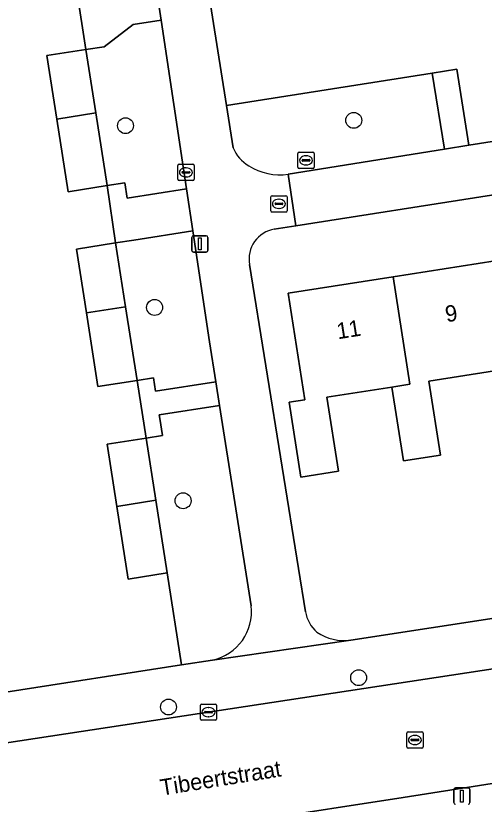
# Model space of a CAD drawing. Extents: x 160077 to 160948, y 386481 to 387498.
# Drawn here: x 160386.76 to 160415.56, y 387278.08 to 387326.58 of the extents above; entities that cross this region are included whole.
import ezdxf

# ---------------------------------------------------------------- set-up
doc = ezdxf.new("R2010")
doc.units = 0
for name, color, linetype in [('IMGEO_Boom', 7, 'Continuous'), ('IMGEO_Brandkraan', 7, 'Continuous'), ('IMGEO_Erf', 7, 'Continuous'), ('IMGEO_Groenvoorziening', 7, 'Continuous'), ('IMGEO_Kolk', 7, 'Continuous'), ('IMGEO_Lichtmast', 7, 'Continuous'), ('IMGEO_Openbare_ruimte_label', 7, 'Continuous'), ('IMGEO_Pand', 7, 'Continuous'), ('IMGEO_Pand_nummerreeks', 7, 'Continuous'), ('IMGEO_Rijbaan_lokaal_open', 7, 'Continuous'), ('IMGEO_Rioolput', 7, 'Continuous'), ('IMGEO_Voetpad_open', 7, 'Continuous')]:
    doc.layers.add(name, color=color, linetype=linetype)

msp = doc.modelspace()

# ---------------------------------------------------------------- linework, layer by layer
at = {"layer": 'IMGEO_Boom'}
for centre in [(160393.501, 387319.82), (160407.54, 387320.148), (160395.293, 387308.64), (160397.045, 387296.749), (160407.841, 387285.863), (160396.15, 387284.06)]:
    msp.add_circle(centre, 0.489, dxfattribs=at)
at = {"layer": 'IMGEO_Brandkraan'}
for p, q in [((160402.513, 387315.511), (160403.365, 387315.511)), ((160402.438, 387314.585), (160402.438, 387315.437)), ((160402.697, 387315.005), (160402.697, 387315.017)), ((160403.135, 387314.968), (160402.737, 387314.968)), ((160402.74, 387315.054), (160403.138, 387315.054)), ((160402.926, 387315.291), (160402.951, 387315.291)), ((160403.181, 387315.017), (160403.181, 387315.005)), ((160403.439, 387315.437), (160403.439, 387314.585)), ((160403.365, 387314.511), (160402.513, 387314.511)), ((160402.949, 387314.731), (160402.924, 387314.731))]:
    msp.add_line(p, q, dxfattribs=at)
for points in [[(160402.513, 387315.511), (160403.365, 387315.511)], [(160402.438, 387314.585), (160402.438, 387315.437)], [(160403.439, 387315.437), (160403.439, 387314.585)], [(160403.365, 387314.511), (160402.513, 387314.511)]]:
    msp.add_lwpolyline(points, dxfattribs=at)
for centre, radius, start, end in [((160402.515, 387315.435), 0.0765, 91.552, 178.448), ((160402.515, 387315.435), 0.0765, 91.552, 178.448), ((160403.363, 387315.435), 0.0765, 1.552, 88.448), ((160403.363, 387315.435), 0.0765, 1.552, 88.448), ((160402.737, 387315.014), 0.0403, 85.8775, 175.7526), ((160402.734, 387315.004), 0.0366, 178.938, 274.7102), ((160403.138, 387315.011), 0.043, 264.8664, 352.4533), ((160403.142, 387315.016), 0.0386, 1.7309, 96.639), ((160402.515, 387314.587), 0.0765, 181.552, 268.448), ((160402.515, 387314.587), 0.0765, 181.552, 268.448), ((160403.363, 387314.587), 0.0765, 271.552, 358.448), ((160403.363, 387314.587), 0.0765, 271.552, 358.448)]:
    msp.add_arc(centre, radius, start, end, dxfattribs=at)
for centre, major_axis, ratio, start_param, end_param in [((160402.925, 387315.011), (-0.387, 0.002), 0.722429, 4.712389, 7.853982), ((160402.95, 387315.011), (-0.39, 0.002), 0.717154, 1.570796, 4.712389)]:
    msp.add_ellipse(centre, major_axis=major_axis, ratio=ratio, start_param=start_param, end_param=end_param, dxfattribs=at)
at = {"layer": 'IMGEO_Erf'}
for points in [[(160396.716, 387339.967), (160399.712, 387321.067), (160412.37, 387323.056), (160413.879, 387323.293), (160414.621, 387318.615), (160420.12, 387319.489), (160421.491, 387319.707), (160425.074, 387320.276), (160424.333, 387324.945), (160425.392, 387325.112), (160425.675, 387325.157), (160426.301, 387321.22), (160440.954, 387323.546)], [(160375.322, 387283.298), (160396.951, 387286.648), (160396.068, 387292.305), (160393.663, 387291.93), (160392.965, 387296.404), (160392.369, 387300.222), (160394.774, 387300.597), (160394.213, 387304.145), (160391.808, 387303.77), (160391.099, 387308.315), (160390.488, 387312.232), (160392.893, 387312.607), (160392.376, 387316.133), (160389.972, 387315.758), (160389.274, 387320.231), (160388.665, 387324.131), (160391.07, 387324.506), (160390.513, 387328.113), (160388.108, 387327.738), (160387.421, 387332.143)], [(160440.073, 387319.313), (160403.977, 387313.658), (160402.655, 387313.451)], [(160401.131, 387311.289), (160404.14, 387292.577), (160404.567, 387289.922)], [(160416.185, 387304.734), (160412.166, 387304.104), (160412.878, 387299.557), (160410.591, 387299.199), (160409.879, 387303.745), (160405.887, 387303.12), (160406.599, 387298.573), (160404.28, 387298.209), (160403.56, 387302.803), (160404.534, 387302.956), (160403.505, 387309.521), (160409.959, 387310.532), (160416.235, 387311.515)], [(160407.359, 387288.172), (160412.298, 387288.928), (160417.775, 387289.765), (160417.165, 387293.754), (160416.344, 387293.629), (160416.158, 387294.849), (160416.464, 387294.895), (160419.053, 387295.291), (160419.238, 387294.071), (160418.704, 387293.99), (160419.314, 387290), (160443.963, 387293.77)]]:
    msp.add_lwpolyline(points, dxfattribs=at)
for centre, radius, start, end in [((160402.963, 387311.616), 1.861, 99.5237, 190.1161), ((160406.729, 387290.297), 2.194, 189.8286, 228.4264), ((160406.969, 387291.235), 3.088, 236.6785, 277.2481)]:
    msp.add_arc(centre, radius, start, end, dxfattribs=at)
at = {"layer": 'IMGEO_Groenvoorziening'}
for points in [[(160395.697, 387326.317), (160393.978, 387326.046), (160392.194, 387324.68), (160391.07, 387324.506), (160391.679, 387320.602), (160392.376, 387316.133), (160393.466, 387316.301), (160393.613, 387315.369), (160397.255, 387315.946)], [(160397.646, 387313.348), (160394.019, 387312.781), (160392.893, 387312.607), (160393.505, 387308.686), (160394.213, 387304.145), (160395.223, 387304.301), (160395.352, 387303.483), (160399.059, 387304.069), (160398.671, 387306.527)]]:
    msp.add_lwpolyline(points, close=True, dxfattribs=at)
for points in [[(160412.37, 387323.056), (160399.712, 387321.067), (160400.128, 387318.456)], [(160403.511, 387316.844), (160413.113, 387318.38), (160412.37, 387323.056)], [(160399.289, 387302.614), (160395.581, 387302.029), (160395.614, 387301.817), (160395.781, 387300.753), (160394.774, 387300.597), (160395.37, 387296.775), (160396.068, 387292.305), (160396.951, 387286.648), (160398.856, 387286.944)], [(160401.235, 387290.289), (160399.289, 387302.614)]]:
    msp.add_lwpolyline(points, dxfattribs=at)
for centre, radius, start, end in [((160402.16, 387319.269), 2.189, 201.8011, 240.7553), ((160402.959, 387320.195), 3.396, 236.6257, 279.3465), ((160398.192, 387289.935), 3.064, 282.5179, 6.6404)]:
    msp.add_arc(centre, radius, start, end, dxfattribs=at)
at = {"layer": 'IMGEO_Kolk'}
for p, q in [((160396.794, 387317.448), (160397.646, 387317.448)), ((160396.719, 387316.522), (160396.719, 387317.374)), ((160396.978, 387316.942), (160396.978, 387316.954)), ((160397.416, 387316.905), (160397.018, 387316.905)), ((160397.021, 387316.991), (160397.419, 387316.991)), ((160397.207, 387317.228), (160397.232, 387317.228)), ((160397.462, 387316.954), (160397.462, 387316.942)), ((160397.72, 387317.374), (160397.72, 387316.522)), ((160397.646, 387316.448), (160396.794, 387316.448)), ((160397.23, 387316.668), (160397.205, 387316.668)), ((160398.107, 387283.318), (160398.107, 387284.17)), ((160398.182, 387284.244), (160399.034, 387284.244)), ((160398.595, 387284.024), (160398.62, 387284.024)), ((160399.108, 387284.17), (160399.108, 387283.318)), ((160398.366, 387283.738), (160398.366, 387283.75)), ((160398.804, 387283.701), (160398.406, 387283.701)), ((160398.409, 387283.787), (160398.807, 387283.787)), ((160398.618, 387283.464), (160398.593, 387283.464)), ((160398.85, 387283.75), (160398.85, 387283.738)), ((160399.034, 387283.244), (160398.182, 387283.244))]:
    msp.add_line(p, q, dxfattribs=at)
for points in [[(160396.794, 387317.448), (160397.646, 387317.448)], [(160396.719, 387316.522), (160396.719, 387317.374)], [(160397.72, 387317.374), (160397.72, 387316.522)], [(160397.646, 387316.448), (160396.794, 387316.448)], [(160398.107, 387283.318), (160398.107, 387284.17)], [(160398.182, 387284.244), (160399.034, 387284.244)], [(160399.108, 387284.17), (160399.108, 387283.318)], [(160399.034, 387283.244), (160398.182, 387283.244)]]:
    msp.add_lwpolyline(points, dxfattribs=at)
for centre, radius, start, end in [((160396.796, 387317.372), 0.0765, 91.552, 178.448), ((160396.796, 387317.372), 0.0765, 91.552, 178.448), ((160397.644, 387317.372), 0.0765, 1.552, 88.448), ((160397.644, 387317.372), 0.0765, 1.552, 88.448), ((160397.018, 387316.951), 0.0403, 85.8775, 175.7526), ((160397.015, 387316.941), 0.0366, 178.938, 274.7102), ((160397.419, 387316.948), 0.043, 264.8664, 352.4533), ((160397.423, 387316.953), 0.0386, 1.7309, 96.639), ((160396.796, 387316.524), 0.0765, 181.552, 268.448), ((160396.796, 387316.524), 0.0765, 181.552, 268.448), ((160397.644, 387316.524), 0.0765, 271.552, 358.448), ((160397.644, 387316.524), 0.0765, 271.552, 358.448), ((160398.184, 387284.168), 0.0765, 91.552, 178.448), ((160398.184, 387284.168), 0.0765, 91.552, 178.448), ((160399.032, 387284.168), 0.0765, 1.552, 88.448), ((160399.032, 387284.168), 0.0765, 1.552, 88.448), ((160398.406, 387283.747), 0.0403, 85.8775, 175.7526), ((160398.403, 387283.737), 0.0366, 178.938, 274.7102), ((160398.807, 387283.744), 0.043, 264.8664, 352.4533), ((160398.811, 387283.749), 0.0386, 1.7309, 96.639), ((160398.184, 387283.32), 0.0765, 181.552, 268.448), ((160398.184, 387283.32), 0.0765, 181.552, 268.448), ((160399.032, 387283.32), 0.0765, 271.552, 358.448), ((160399.032, 387283.32), 0.0765, 271.552, 358.448)]:
    msp.add_arc(centre, radius, start, end, dxfattribs=at)
for centre, major_axis, ratio, start_param, end_param in [((160397.206, 387316.948), (-0.387, 0.002), 0.722429, 4.712389, 7.853982), ((160397.231, 387316.948), (-0.39, 0.002), 0.717154, 1.570796, 4.712389), ((160398.594, 387283.744), (-0.387, 0.002), 0.722429, 4.712389, 7.853982), ((160398.619, 387283.744), (-0.39, 0.002), 0.717154, 1.570796, 4.712389)]:
    msp.add_ellipse(centre, major_axis=major_axis, ratio=ratio, start_param=start_param, end_param=end_param, dxfattribs=at)
at = {"layer": 'IMGEO_Lichtmast'}
for p, q in [((160397.679, 387313.05), (160398.469, 387313.05)), ((160398.469, 387313.05), (160397.679, 387313.05)), ((160397.579, 387312.15), (160397.579, 387312.95)), ((160397.579, 387312.95), (160397.579, 387312.15)), ((160398.569, 387312.95), (160398.569, 387312.15)), ((160398.569, 387312.15), (160398.569, 387312.95)), ((160398.469, 387312.05), (160397.679, 387312.05)), ((160397.679, 387312.05), (160398.469, 387312.05)), ((160413.793, 387279.079), (160414.583, 387279.079)), ((160414.583, 387279.079), (160413.793, 387279.079)), ((160413.693, 387278.179), (160413.693, 387278.979)), ((160413.693, 387278.979), (160413.693, 387278.179)), ((160414.683, 387278.979), (160414.683, 387278.179)), ((160414.683, 387278.179), (160414.683, 387278.979))]:
    msp.add_line(p, q, dxfattribs=at)
for points in [[(160397.999, 387312.925), (160398.149, 387312.925), (160398.149, 387312.175), (160397.999, 387312.175), (160397.999, 387312.925)], [(160414.113, 387278.954), (160414.263, 387278.954), (160414.263, 387278.204), (160414.113, 387278.204), (160414.113, 387278.954)]]:
    msp.add_lwpolyline(points, dxfattribs=at)
for centre, start, end in [((160397.679, 387312.95), 90, 180), ((160397.679, 387312.95), 90, 180), ((160398.469, 387312.95), 0, 90), ((160398.469, 387312.95), 360, 90), ((160397.679, 387312.15), 180, 270), ((160397.679, 387312.15), 180, 270), ((160398.469, 387312.15), 270, 0), ((160398.469, 387312.15), 270, 0), ((160413.793, 387278.979), 90, 180), ((160413.793, 387278.979), 90, 180), ((160414.583, 387278.979), 0, 90), ((160414.583, 387278.979), 360, 90), ((160413.793, 387278.179), 180, 270), ((160413.793, 387278.179), 180, 270), ((160414.583, 387278.179), 270, 0), ((160414.583, 387278.179), 270, 0)]:
    msp.add_arc(centre, 0.1, start, end, dxfattribs=at)
at = {"layer": 'IMGEO_Pand'}
for points in [[(160391.07, 387324.506), (160388.665, 387324.131), (160389.274, 387320.231), (160391.679, 387320.602)], [(160391.679, 387320.602), (160389.274, 387320.231), (160389.972, 387315.758), (160392.376, 387316.133)], [(160392.893, 387312.607), (160390.488, 387312.232), (160391.099, 387308.315), (160393.505, 387308.686)], [(160417.27, 387304.905), (160416.235, 387311.515), (160409.959, 387310.532), (160410.995, 387303.919), (160409.879, 387303.745), (160410.591, 387299.199), (160412.878, 387299.557), (160412.166, 387304.104), (160416.185, 387304.734)], [(160410.995, 387303.919), (160409.959, 387310.532), (160403.505, 387309.521), (160404.534, 387302.956), (160403.56, 387302.803), (160404.28, 387298.209), (160406.599, 387298.573), (160405.887, 387303.12), (160409.879, 387303.745)], [(160393.505, 387308.686), (160391.099, 387308.315), (160391.808, 387303.77), (160394.213, 387304.145)], [(160394.774, 387300.597), (160392.369, 387300.222), (160392.965, 387296.404), (160395.37, 387296.775)], [(160395.37, 387296.775), (160392.965, 387296.404), (160393.663, 387291.93), (160396.068, 387292.305)]]:
    msp.add_lwpolyline(points, close=True, dxfattribs=at)
at = {"layer": 'IMGEO_Rijbaan_lokaal_open'}
for points in [[(160444.411, 387290.851), (160417.322, 387286.585), (160375.933, 387280.299)], [(160397.338, 387276.443), (160401.538, 387277.092), (160410.581, 387278.491), (160447.213, 387284.258)]]:
    msp.add_lwpolyline(points, dxfattribs=at)
at = {"layer": 'IMGEO_Rioolput'}
for p, q in [((160404.103, 387317.264), (160404.103, 387318.116)), ((160404.178, 387318.19), (160405.03, 387318.19)), ((160404.591, 387317.97), (160404.616, 387317.97)), ((160405.104, 387318.116), (160405.104, 387317.264)), ((160404.362, 387317.684), (160404.362, 387317.696)), ((160404.8, 387317.647), (160404.402, 387317.647)), ((160404.405, 387317.733), (160404.803, 387317.733)), ((160404.614, 387317.41), (160404.589, 387317.41)), ((160404.846, 387317.696), (160404.846, 387317.684)), ((160405.03, 387317.19), (160404.178, 387317.19)), ((160410.876, 387282.532), (160411.728, 387282.532)), ((160410.801, 387281.606), (160410.801, 387282.458)), ((160411.06, 387282.026), (160411.06, 387282.038)), ((160411.498, 387281.989), (160411.1, 387281.989)), ((160411.103, 387282.075), (160411.501, 387282.075)), ((160411.289, 387282.312), (160411.314, 387282.312)), ((160411.544, 387282.038), (160411.544, 387282.026)), ((160411.802, 387282.458), (160411.802, 387281.606)), ((160411.728, 387281.532), (160410.876, 387281.532)), ((160411.312, 387281.752), (160411.287, 387281.752))]:
    msp.add_line(p, q, dxfattribs=at)
for points in [[(160404.103, 387317.264), (160404.103, 387318.116)], [(160404.178, 387318.19), (160405.03, 387318.19)], [(160405.104, 387318.116), (160405.104, 387317.264)], [(160405.03, 387317.19), (160404.178, 387317.19)], [(160410.876, 387282.532), (160411.728, 387282.532)], [(160410.801, 387281.606), (160410.801, 387282.458)], [(160411.802, 387282.458), (160411.802, 387281.606)], [(160411.728, 387281.532), (160410.876, 387281.532)]]:
    msp.add_lwpolyline(points, dxfattribs=at)
for centre, radius, start, end in [((160404.18, 387318.114), 0.0765, 91.552, 178.448), ((160404.18, 387318.114), 0.0765, 91.552, 178.448), ((160405.028, 387318.114), 0.0765, 1.552, 88.448), ((160405.028, 387318.114), 0.0765, 1.552, 88.448), ((160404.402, 387317.693), 0.0403, 85.8775, 175.7526), ((160404.399, 387317.683), 0.0366, 178.938, 274.7102), ((160404.803, 387317.69), 0.043, 264.8664, 352.4533), ((160404.807, 387317.695), 0.0386, 1.7309, 96.639), ((160404.18, 387317.266), 0.0765, 181.552, 268.448), ((160404.18, 387317.266), 0.0765, 181.552, 268.448), ((160405.028, 387317.266), 0.0765, 271.552, 358.448), ((160405.028, 387317.266), 0.0765, 271.552, 358.448), ((160410.878, 387282.456), 0.0765, 91.552, 178.448), ((160410.878, 387282.456), 0.0765, 91.552, 178.448), ((160411.726, 387282.456), 0.0765, 1.552, 88.448), ((160411.726, 387282.456), 0.0765, 1.552, 88.448), ((160411.1, 387282.035), 0.0403, 85.8775, 175.7526), ((160411.097, 387282.025), 0.0366, 178.938, 274.7102), ((160411.501, 387282.032), 0.043, 264.8664, 352.4533), ((160411.505, 387282.037), 0.0386, 1.7309, 96.639), ((160410.878, 387281.608), 0.0765, 181.552, 268.448), ((160410.878, 387281.608), 0.0765, 181.552, 268.448), ((160411.726, 387281.608), 0.0765, 271.552, 358.448), ((160411.726, 387281.608), 0.0765, 271.552, 358.448)]:
    msp.add_arc(centre, radius, start, end, dxfattribs=at)
for centre, major_axis, ratio, start_param, end_param in [((160404.59, 387317.69), (-0.387, 0.002), 0.722429, 4.712389, 7.853982), ((160404.615, 387317.69), (-0.39, 0.002), 0.717154, 1.570796, 4.712389), ((160411.288, 387282.032), (-0.387, 0.002), 0.722429, 4.712389, 7.853982), ((160411.313, 387282.032), (-0.39, 0.002), 0.717154, 1.570796, 4.712389)]:
    msp.add_ellipse(centre, major_axis=major_axis, ratio=ratio, start_param=start_param, end_param=end_param, dxfattribs=at)
at = {"layer": 'IMGEO_Voetpad_open'}
for points in [[(160430.145, 387379.577), (160418.286, 387377.731), (160416.822, 387377.502), (160405.786, 387375.784), (160404.282, 387375.55), (160393.162, 387373.819), (160391.68, 387373.588), (160388.401, 387373.077), (160389.872, 387363.761), (160389.951, 387363.262), (160390.132, 387362.112), (160391.781, 387351.669), (160392.147, 387349.353), (160393.636, 387339.927), (160393.699, 387339.525), (160394.01, 387337.537), (160395.254, 387329.259), (160395.697, 387326.317), (160397.255, 387315.946), (160397.646, 387313.348), (160398.671, 387306.527), (160399.059, 387304.069), (160399.289, 387302.614), (160401.235, 387290.289)], [(160400.128, 387318.456), (160399.712, 387321.067), (160396.716, 387339.967)], [(160439.928, 387322.624), (160426.417, 387320.489), (160425.074, 387320.276), (160421.491, 387319.707), (160420.12, 387319.489), (160414.621, 387318.615), (160413.113, 387318.38), (160403.511, 387316.844), (160403.977, 387313.658), (160440.073, 387319.313)], [(160402.655, 387313.451), (160403.977, 387313.658), (160403.511, 387316.844)], [(160404.567, 387289.922), (160404.14, 387292.577), (160401.131, 387311.289)], [(160443.963, 387293.77), (160419.314, 387290), (160417.775, 387289.765), (160412.298, 387288.928), (160407.359, 387288.172), (160407.359, 387288.17), (160398.856, 387286.944), (160396.951, 387286.648), (160375.322, 387283.298)], [(160375.933, 387280.299), (160417.322, 387286.585), (160444.411, 387290.851)], [(160398.856, 387286.944), (160407.359, 387288.17), (160407.359, 387288.172)], [(160447.213, 387284.258), (160410.581, 387278.491), (160401.538, 387277.092), (160401.614, 387276.599), (160397.414, 387275.949), (160397.338, 387276.443), (160376.94, 387273.288)]]:
    msp.add_lwpolyline(points, dxfattribs=at)
for points in [[(160395.254, 387329.259), (160390.452, 387328.501), (160390.513, 387328.113), (160391.07, 387324.506), (160392.194, 387324.68), (160393.978, 387326.046), (160395.697, 387326.317)], [(160413.879, 387323.293), (160412.37, 387323.056), (160413.113, 387318.38), (160414.621, 387318.615)], [(160397.255, 387315.946), (160393.613, 387315.369), (160393.466, 387316.301), (160392.376, 387316.133), (160392.893, 387312.607), (160394.019, 387312.781), (160397.646, 387313.348)], [(160399.059, 387304.069), (160395.352, 387303.483), (160395.223, 387304.301), (160394.213, 387304.145), (160394.774, 387300.597), (160395.781, 387300.753), (160395.614, 387301.817), (160395.581, 387302.029), (160399.289, 387302.614)]]:
    msp.add_lwpolyline(points, close=True, dxfattribs=at)
for centre, radius, start, end in [((160402.16, 387319.269), 2.189, 201.8011, 240.7553), ((160402.959, 387320.195), 3.396, 236.6257, 279.3465), ((160402.963, 387311.616), 1.861, 99.5237, 190.1161), ((160398.192, 387289.935), 3.064, 282.5179, 6.6404), ((160406.729, 387290.297), 2.194, 189.8286, 228.4264), ((160406.969, 387291.235), 3.088, 236.6785, 277.2481)]:
    msp.add_arc(centre, radius, start, end, dxfattribs=at)

# ---------------------------------------------------------------- texts
at = {"layer": 'IMGEO_Openbare_ruimte_label'}
msp.add_text('Tibeertstraat', height=1, rotation=9.1514, dxfattribs=at).set_placement((160395.718, 387278.605))
at = {"layer": 'IMGEO_Pand_nummerreeks'}
for s, p in [('9', (160413.244, 387307.727)), ('11', (160406.567, 387306.68))]:
    msp.add_text(s, height=1, rotation=8.904, dxfattribs=at).set_placement(p)

doc.saveas('drawing.dxf')
